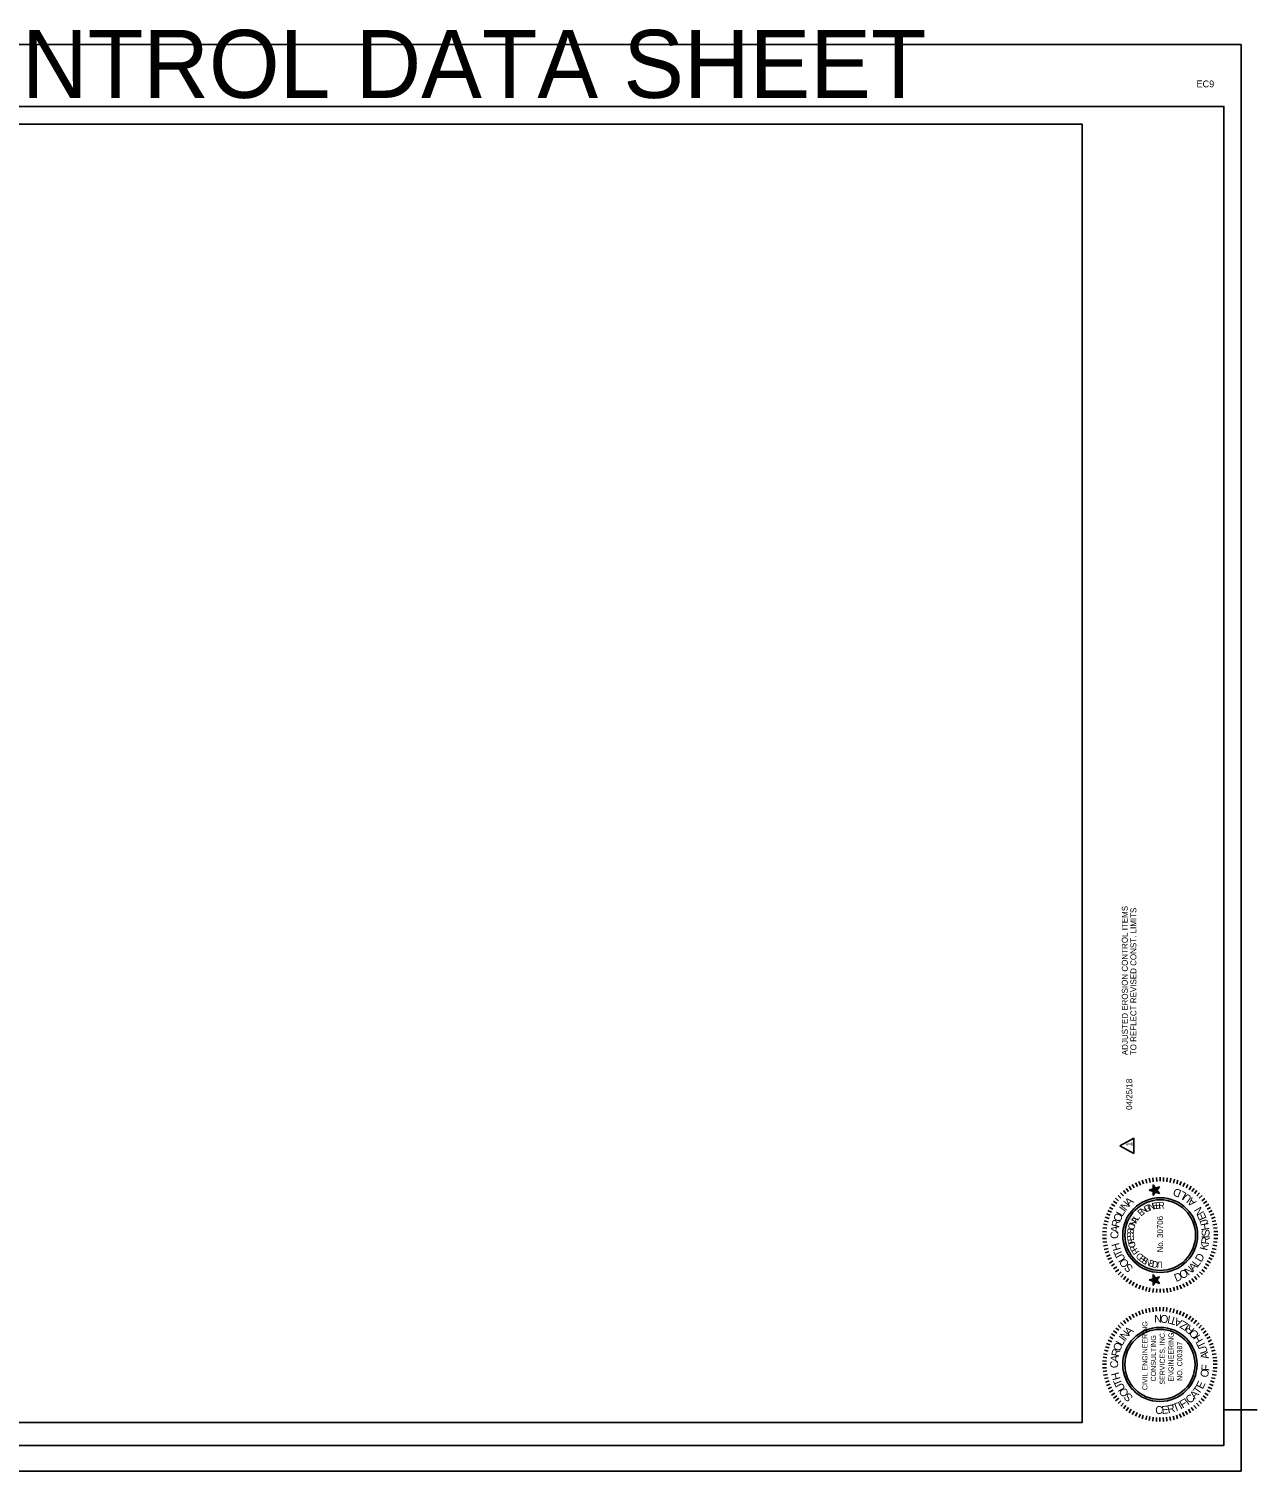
# Model space of a CAD drawing. Extents: x 260980 to 262786, y 322333 to 323393.
import ezdxf

# ---------------------------------------------------------------- set-up
doc = ezdxf.new("R2010")
doc.units = 0
for name, color, linetype in [('Level 1', 7, 'Continuous'), ('Level 2', 7, 'Continuous'), ('Level 23', 7, 'Continuous'), ('Level 3', 7, 'Continuous'), ('Level 4', 7, 'Continuous'), ('Level 8', 7, 'Continuous'), ('RD_SHT_SEAL_KA', 7, 'Continuous'), ('RD_SHT_TX', 7, 'Continuous')]:
    doc.layers.add(name, color=color, linetype=linetype)

msp = doc.modelspace()

# ---------------------------------------------------------------- linework, layer by layer
at = {"layer": 'Level 1'}
msp.add_lwpolyline([(261216, 323323.3), (262657.4, 323323.3), (262657.4, 322368.7), (261216, 322368.7)], close=True, dxfattribs=at)
at = {"layer": 'Level 2'}
msp.add_lwpolyline([(261216, 322368.7), (262657.4, 322368.7), (262657.4, 323323.3), (261216, 323323.3)], close=True, dxfattribs=at)
at = {"layer": 'Level 23'}
msp.add_lwpolyline([(261111.1, 323336.4), (262761.5, 323336.4), (262761.5, 322351.8), (261111.1, 322351.8)], close=True, dxfattribs=at)
msp.add_lwpolyline([(261111.1, 323336.4), (262761.5, 323336.4), (262761.5, 322351.8), (261111.1, 322351.8)], close=True, dxfattribs=at)
at = {"layer": 'Level 3'}
for p, q in [((261099.2, 323381.9), (262774.2, 323381.9)), ((262774.2, 322332.8), (262774.2, 323381.9)), ((261099.2, 322332.9), (262774.2, 322332.9))]:
    msp.add_line(p, q, dxfattribs=at)
at = {"layer": 'Level 4'}
msp.add_line((262762, 322377.8), (262786, 322377.8), dxfattribs=at)
at = {"layer": 'RD_SHT_SEAL_KA'}
for p, q in [((262694.2, 322543.6), (262695.6, 322541.1)), ((262696.6, 322544.8), (262697.9, 322542.2)), ((262699, 322545.9), (262700.1, 322543.2)), ((262701.5, 322546.8), (262702.5, 322544.1)), ((262704.1, 322547.6), (262704.8, 322544.7)), ((262706.7, 322548.2), (262707.3, 322545.2)), ((262709.4, 322548.6), (262709.6, 322545.7)), ((262712, 322548.7), (262712.2, 322545.9)), ((262714.7, 322548.9), (262714.6, 322546)), ((262717.2, 322548.7), (262717.1, 322545.9)), ((262719.9, 322548.5), (262719.7, 322545.6)), ((262722.6, 322548.2), (262722.1, 322545.2)), ((262725.2, 322547.6), (262724.4, 322544.7)), ((262727.7, 322546.8), (262726.9, 322544.1)), ((262730.2, 322545.9), (262729.2, 322543.1)), ((262732.7, 322544.8), (262731.4, 322542.2)), ((262735.1, 322543.6), (262733.7, 322541.1)), ((262681.9, 322533.5), (262684.1, 322531.6)), ((262683.7, 322535.5), (262685.8, 322533.6)), ((262685.6, 322537.4), (262687.6, 322535.2)), ((262687.6, 322539.1), (262689.4, 322536.9)), ((262689.7, 322540.7), (262691.4, 322538.4)), ((262691.9, 322542.3), (262693.4, 322539.8)), ((262737.4, 322542.3), (262735.9, 322539.8)), ((262739.6, 322540.8), (262737.9, 322538.4)), ((262741.7, 322539.2), (262739.8, 322536.9)), ((262743.7, 322537.4), (262741.7, 322535.3)), ((262745.6, 322535.5), (262743.4, 322533.5)), ((262747.4, 322533.4), (262745.2, 322531.6)), ((262675.2, 322522.1), (262677.9, 322521)), ((262676.3, 322524.4), (262678.9, 322523.2)), ((262677.4, 322526.8), (262679.9, 322525.5)), ((262678.9, 322529.2), (262681.3, 322527.6)), ((262680.3, 322531.4), (262682.7, 322529.7)), ((262748.9, 322531.4), (262746.6, 322529.7)), ((262750.5, 322529.1), (262748.1, 322527.6)), ((262751.8, 322526.8), (262749.3, 322525.5)), ((262753, 322524.6), (262750.4, 322523.3)), ((262754.1, 322522.1), (262751.4, 322521)), ((262672.5, 322511.8), (262675.5, 322511.4)), ((262673, 322514.4), (262675.8, 322513.9)), ((262673.6, 322517), (262676.4, 322516.2)), ((262674.3, 322519.5), (262677.1, 322518.7)), ((262755, 322519.5), (262752.3, 322518.7)), ((262755.7, 322517), (262752.9, 322516.3)), ((262756.3, 322514.4), (262753.5, 322513.9)), ((262756.7, 322511.7), (262753.9, 322511.4)), ((262672.3, 322509), (262675.3, 322508.8)), ((262672.3, 322506.5), (262675.1, 322506.4)), ((262672.3, 322503.8), (262675.2, 322503.9)), ((262672.6, 322501.2), (262675.4, 322501.5)), ((262756.7, 322501.1), (262753.9, 322501.5)), ((262757.1, 322509.1), (262754.1, 322509)), ((262757, 322503.8), (262754.1, 322504)), ((262757, 322506.5), (262754.2, 322506.5)), ((262673, 322498.5), (262675.9, 322499)), ((262673.6, 322495.8), (262676.4, 322496.6)), ((262674.3, 322493.3), (262677, 322494.3)), ((262675.2, 322490.8), (262677.9, 322491.9)), ((262754.1, 322490.8), (262751.4, 322491.9)), ((262755, 322493.3), (262752.2, 322494.2)), ((262755.8, 322495.9), (262752.9, 322496.5)), ((262756.3, 322498.5), (262753.4, 322499)), ((262676.3, 322488.4), (262678.9, 322489.6)), ((262677.4, 322485.9), (262680, 322487.4)), ((262678.9, 322483.7), (262681.2, 322485.2)), ((262680.4, 322481.5), (262682.7, 322483.2)), ((262681.9, 322479.4), (262684.2, 322481.2)), ((262683.7, 322477.3), (262685.9, 322479.4)), ((262745.7, 322477.5), (262743.5, 322479.4)), ((262747.3, 322479.4), (262745.2, 322481.2)), ((262748.9, 322481.5), (262746.7, 322483.2)), ((262750.5, 322483.7), (262748, 322485.2)), ((262751.8, 322486), (262749.3, 322487.4)), ((262753, 322488.4), (262750.4, 322489.6)), ((262685.7, 322475.5), (262687.6, 322477.6)), ((262687.6, 322473.7), (262689.4, 322476)), ((262689.7, 322472.1), (262691.4, 322474.5)), ((262691.9, 322470.6), (262693.5, 322473.1)), ((262694.2, 322469.3), (262695.6, 322471.8)), ((262696.6, 322468), (262697.8, 322470.6)), ((262699, 322467), (262700.1, 322469.7)), ((262701.6, 322466.1), (262702.5, 322468.8)), ((262727.7, 322466.1), (262726.9, 322468.8)), ((262730.3, 322466.9), (262729.2, 322469.7)), ((262732.7, 322468.1), (262731.4, 322470.7)), ((262735.1, 322469.2), (262733.7, 322471.8)), ((262737.4, 322470.7), (262735.9, 322473)), ((262739.6, 322472.1), (262737.9, 322474.4)), ((262741.7, 322473.7), (262739.9, 322476)), ((262743.7, 322475.5), (262741.7, 322477.6)), ((262704.1, 322465.3), (262704.8, 322468.2)), ((262706.7, 322464.8), (262707.2, 322467.6)), ((262709.4, 322464.3), (262709.7, 322467.2)), ((262712, 322464.1), (262712.2, 322467)), ((262714.7, 322464.1), (262714.7, 322466.9)), ((262717.3, 322464.1), (262717.1, 322466.9)), ((262720, 322464.3), (262719.6, 322467.3)), ((262722.6, 322464.7), (262722.1, 322467.5)), ((262725.2, 322465.4), (262724.5, 322468.1)), ((262694.1, 322448.3), (262695.6, 322445.7)), ((262696.5, 322449.3), (262697.7, 322446.9)), ((262698.9, 322450.4), (262700, 322447.8)), ((262701.4, 322451.4), (262702.3, 322448.6)), ((262704.1, 322452.1), (262704.6, 322449.3)), ((262706.6, 322452.6), (262707.2, 322449.8)), ((262709.2, 322453.2), (262709.6, 322450.1)), ((262711.8, 322453.3), (262712, 322450.4)), ((262714.4, 322453.3), (262714.5, 322450.6)), ((262717.1, 322453.3), (262716.9, 322450.4)), ((262719.7, 322453.1), (262719.4, 322450.2)), ((262722.4, 322452.6), (262721.9, 322449.8)), ((262724.9, 322452.1), (262724.2, 322449.3)), ((262727.4, 322451.3), (262726.6, 322448.6)), ((262729.9, 322450.4), (262728.9, 322447.8)), ((262732.3, 322449.4), (262731.2, 322446.9)), ((262734.8, 322448.2), (262733.4, 322445.6)), ((262682, 322438.1), (262684.3, 322436.4)), ((262683.8, 322440.1), (262685.8, 322438.1)), ((262685.6, 322442.1), (262687.6, 322439.9)), ((262687.6, 322443.7), (262689.5, 322441.5)), ((262689.7, 322445.4), (262691.4, 322443)), ((262691.9, 322446.9), (262693.4, 322444.4)), ((262737.2, 322446.9), (262735.5, 322444.4)), ((262739.3, 322445.3), (262737.5, 322443)), ((262741.3, 322443.8), (262739.5, 322441.5)), ((262743.3, 322442), (262741.3, 322439.9)), ((262745.1, 322440.1), (262743, 322438.1)), ((262747, 322438.1), (262744.7, 322436.4)), ((262675.3, 322426.8), (262678, 322425.8)), ((262676.4, 322429.2), (262679.1, 322428)), ((262677.6, 322431.6), (262680, 322430.1)), ((262679, 322433.9), (262681.4, 322432.3)), ((262680.3, 322436), (262682.7, 322434.3)), ((262748.5, 322436), (262746.3, 322434.4)), ((262750, 322433.8), (262747.6, 322432.3)), ((262751.4, 322431.6), (262748.9, 322430.3)), ((262752.5, 322429.3), (262749.9, 322428)), ((262753.6, 322426.8), (262750.9, 322425.7)), ((262672.7, 322416.6), (262675.5, 322416.2)), ((262673.1, 322419.2), (262675.8, 322418.7)), ((262673.7, 322421.8), (262676.5, 322421.1)), ((262674.4, 322424.3), (262677.2, 322423.5)), ((262754.5, 322424.3), (262751.8, 322423.4)), ((262755.2, 322421.8), (262752.4, 322421.1)), ((262755.8, 322419.1), (262753, 322418.7)), ((262756.3, 322416.5), (262753.4, 322416.2)), ((262672.3, 322411.4), (262675.2, 322411.4)), ((262672.4, 322414), (262675.3, 322413.8)), ((262672.4, 322408.7), (262675.3, 322408.9)), ((262672.8, 322406.1), (262675.5, 322406.5)), ((262756.3, 322406), (262753.4, 322406.5)), ((262756.5, 322414), (262753.6, 322413.9)), ((262756.5, 322408.8), (262753.6, 322408.9)), ((262756.5, 322411.4), (262753.7, 322411.4)), ((262673.1, 322403.5), (262676, 322404)), ((262673.7, 322400.9), (262676.5, 322401.5)), ((262674.5, 322398.3), (262677.2, 322399.2)), ((262675.3, 322395.9), (262678, 322396.9)), ((262676.4, 322393.4), (262679, 322394.7)), ((262752.6, 322393.4), (262749.9, 322394.6)), ((262753.6, 322395.8), (262751, 322396.9)), ((262754.5, 322398.3), (262751.8, 322399.2)), ((262755.2, 322400.9), (262752.4, 322401.5)), ((262755.8, 322403.5), (262753, 322404)), ((262677.5, 322391), (262680.1, 322392.4)), ((262679, 322388.8), (262681.3, 322390.3)), ((262680.4, 322386.6), (262682.7, 322388.2)), ((262681.9, 322384.6), (262684.3, 322386.4)), ((262683.8, 322382.5), (262685.8, 322384.6)), ((262745.1, 322382.6), (262743, 322384.6)), ((262747, 322384.6), (262744.7, 322386.3)), ((262748.5, 322386.6), (262746.2, 322388.3)), ((262750, 322388.8), (262747.6, 322390.3)), ((262751.4, 322391.1), (262748.9, 322392.5)), ((262685.7, 322380.7), (262687.6, 322382.9)), ((262687.6, 322378.8), (262689.5, 322381.1)), ((262689.7, 322377.3), (262691.4, 322379.6)), ((262691.9, 322375.8), (262693.4, 322378.3)), ((262694.2, 322374.5), (262695.6, 322376.9)), ((262696.5, 322373.3), (262697.7, 322375.9)), ((262699, 322372.2), (262700.1, 322374.8)), ((262701.5, 322371.3), (262702.3, 322374.1)), ((262704.1, 322370.6), (262704.8, 322373.4)), ((262725, 322370.6), (262724.2, 322373.3)), ((262727.4, 322371.4), (262726.6, 322374.1)), ((262730, 322372.2), (262728.9, 322374.9)), ((262732.5, 322373.3), (262731.1, 322376)), ((262734.8, 322374.5), (262733.3, 322376.9)), ((262737, 322375.8), (262735.5, 322378.3)), ((262739.3, 322377.4), (262737.5, 322379.6)), ((262741.3, 322378.9), (262739.5, 322381.1)), ((262743.3, 322380.7), (262741.3, 322382.9)), ((262706.6, 322370), (262707.1, 322372.9)), ((262709.2, 322369.6), (262709.6, 322372.5)), ((262711.9, 322369.4), (262712.1, 322372.2)), ((262714.4, 322369.4), (262714.5, 322372.2)), ((262717.1, 322369.4), (262716.9, 322372.3)), ((262719.7, 322369.6), (262719.4, 322372.5)), ((262722.3, 322370), (262721.8, 322372.8))]:
    msp.add_line(p, q, dxfattribs=at)
for points in [[(262706.7, 322539.5), (262709.5, 322538.5), (262709.6, 322535.7), (262711.3, 322538.1), (262714.1, 322537.1), (262712.3, 322539.5), (262714.1, 322541.9), (262711.3, 322540.9), (262709.5, 322543.3), (262709.5, 322540.4)], [(262707.1, 322539.5), (262709.6, 322538.7), (262709.7, 322536), (262711.3, 322538.2), (262713.8, 322537.4), (262712.3, 322539.5), (262713.8, 322541.7), (262711.3, 322540.9), (262709.6, 322543), (262709.7, 322540.3)], [(262707.5, 322539.5), (262709.8, 322538.8), (262709.8, 322536.4), (262711.2, 322538.3), (262713.5, 322537.6), (262712.1, 322539.5), (262713.5, 322541.5), (262711.3, 322540.7), (262709.7, 322542.6), (262709.8, 322540.3)], [(262707.9, 322539.5), (262710, 322538.9), (262710, 322536.8), (262711.1, 322538.5), (262713.1, 322537.7), (262711.9, 322539.5), (262713.1, 322541.2), (262711.1, 322540.5), (262709.9, 322542.3), (262709.9, 322540.2)], [(262708.3, 322539.5), (262710.1, 322538.9), (262710, 322537.1), (262711, 322538.5), (262712.9, 322538.1), (262711.8, 322539.5), (262712.8, 322540.9), (262711.1, 322540.4), (262710.1, 322541.9), (262710, 322540.1)], [(262708.7, 322539.6), (262710.1, 322539), (262710.1, 322537.5), (262711, 322538.8), (262712.5, 322538.2), (262711.6, 322539.5), (262712.5, 322540.7), (262711.1, 322540.3), (262710.2, 322541.5), (262710.1, 322540)], [(262709.1, 322539.5), (262710.2, 322539.1), (262710.3, 322537.8), (262711, 322538.9), (262712.2, 322538.5), (262711.4, 322539.5), (262712.2, 322540.5), (262711, 322540.1), (262710.3, 322541.2), (262710.2, 322539.9)], [(262709.5, 322539.5), (262710.4, 322539.2), (262710.4, 322538.2), (262711, 322539), (262711.8, 322538.7), (262711.4, 322539.5), (262711.9, 322540.3), (262711, 322540), (262710.4, 322540.7), (262710.4, 322539.8)], [(262709.8, 322539.5), (262710.5, 322539.2), (262710.6, 322538.7), (262710.9, 322539.1), (262711.5, 322538.9), (262711.2, 322539.5), (262711.6, 322540.1), (262711, 322539.8), (262710.6, 322540.4), (262710.5, 322539.8)], [(262710.2, 322539.5), (262710.6, 322539.4), (262710.6, 322539), (262710.9, 322539.4), (262711.3, 322539.1), (262711, 322539.6), (262711.3, 322539.8), (262710.9, 322539.7), (262710.6, 322540.1), (262710.7, 322539.7)], [(262710.7, 322539.6), (262710.8, 322539.5), (262710.8, 322539.4), (262710.8, 322539.4), (262711, 322539.4), (262710.9, 322539.5), (262710.9, 322539.6), (262710.8, 322539.6), (262710.8, 322539.6), (262710.8, 322539.5)], [(262706.7, 322473.4), (262709.6, 322472.4), (262709.6, 322469.5), (262711.4, 322471.9), (262714.1, 322470.9), (262712.3, 322473.4), (262714.1, 322475.7), (262711.3, 322474.8), (262709.5, 322477.2), (262709.5, 322474.3)], [(262707.1, 322473.3), (262709.6, 322472.6), (262709.6, 322469.9), (262711.3, 322472), (262713.8, 322471.2), (262712.2, 322473.3), (262713.8, 322475.5), (262711.2, 322474.7), (262709.7, 322476.9), (262709.6, 322474.2)], [(262707.5, 322473.4), (262709.8, 322472.6), (262709.8, 322470.2), (262711.2, 322472.2), (262713.5, 322471.5), (262712.1, 322473.4), (262713.5, 322475.3), (262711.1, 322474.5), (262709.8, 322476.5), (262709.8, 322474.1)], [(262707.9, 322473.4), (262709.9, 322472.7), (262710, 322470.6), (262711.1, 322472.3), (262713.1, 322471.7), (262711.9, 322473.3), (262713.1, 322475.1), (262711.1, 322474.5), (262709.8, 322476.1), (262710, 322474)], [(262708.3, 322473.4), (262710, 322472.8), (262710.1, 322471), (262711.1, 322472.4), (262712.9, 322471.9), (262711.7, 322473.4), (262712.9, 322474.9), (262711.1, 322474.3), (262710, 322475.7), (262710, 322474)], [(262708.7, 322473.4), (262710.2, 322472.9), (262710.1, 322471.4), (262711, 322472.6), (262712.5, 322472.1), (262711.6, 322473.4), (262712.5, 322474.7), (262711, 322474.1), (262710.2, 322475.4), (262710.2, 322473.9)], [(262709.1, 322473.4), (262710.2, 322473), (262710.4, 322471.7), (262711, 322472.8), (262712.2, 322472.4), (262711.5, 322473.3), (262712.2, 322474.4), (262711, 322474.1), (262710.3, 322475), (262710.3, 322473.7)], [(262709.5, 322473.4), (262710.4, 322473.1), (262710.4, 322472.1), (262710.9, 322472.9), (262711.8, 322472.6), (262711.4, 322473.4), (262711.9, 322474.2), (262711, 322473.9), (262710.4, 322474.7), (262710.3, 322473.6)], [(262709.9, 322473.4), (262710.5, 322473.1), (262710.5, 322472.4), (262710.9, 322473), (262711.5, 322472.9), (262711.1, 322473.4), (262711.6, 322473.9), (262710.9, 322473.7), (262710.6, 322474.3), (262710.5, 322473.6)], [(262710.2, 322473.4), (262710.6, 322473.2), (262710.6, 322472.9), (262710.9, 322473.2), (262711.3, 322473), (262711, 322473.4), (262711.3, 322473.6), (262710.8, 322473.5), (262710.7, 322473.9), (262710.7, 322473.5)], [(262710.7, 322473.4), (262710.8, 322473.4), (262710.8, 322473.1), (262710.8, 322473.3), (262710.9, 322473.3), (262710.9, 322473.4), (262710.9, 322473.4), (262710.8, 322473.4), (262710.7, 322473.6), (262710.7, 322473.4)]]:
    msp.add_lwpolyline(points, close=True, dxfattribs=at)
for radius in [27.5, 26]:
    msp.add_circle((262714.7, 322506.4), radius, dxfattribs=at)
for major_axis in [(-27.3, 0), (-25.8, 0)]:
    msp.add_ellipse((262714.5, 322411.3), major_axis=major_axis, ratio=0.998589, dxfattribs=at)
at = {"layer": 'RD_SHT_TX'}
for p, q in [((262695.3, 322577.8), (262685.1, 322572.1)), ((262695.3, 322566.4), (262695.3, 322577.8)), ((262685.1, 322572.1), (262695.3, 322566.4))]:
    msp.add_line(p, q, dxfattribs=at)

# ---------------------------------------------------------------- texts
at = {"layer": 'Level 3'}
msp.add_text('EC9', height=5, dxfattribs=at).set_placement((262741.4, 323350.5))
at = {"layer": 'Level 8'}
msp.add_text('EROSION CONTROL DATA SHEET', height=50, dxfattribs=at).set_placement((261450.7, 323342.7))
at = {"layer": 'RD_SHT_SEAL_KA'}
for s, height, rotation, p in [('A', 5.79, 43.0946, (262691.9, 322527.2)), ('D', 5.78, 157.437, (262730.8, 322539.1)), ('L', 5.78, 150.6276, (262734.6, 322537)), ('U', 5.78, 143.1014, (262738.4, 322534.1)), ('A', 5.78, 135.9336, (262741.7, 322530.9)), ('O', 5.79, 68.1426, (262685.3, 322515.6)), ('L', 5.79, 59.9125, (262686.9, 322519.7)), ('I', 5.79, 53.1138, (262688.7, 322522.9)), ('N', 5.79, 50.609, (262689.4, 322524.1)), ('E', 4.82, 42.0319, (262700.7, 322520)), ('N', 4.82, 35.5788, (262702.3, 322521.4)), ('G', 4.82, 28.803, (262704.2, 322522.8)), ('I', 4.82, 21.7046, (262706.3, 322524)), ('N', 4.82, 19.446, (262707, 322524.3)), ('E', 4.82, 12.6702, (262709.1, 322525.1)), ('E', 4.82, 6.2171, (262711.3, 322525.6)), ('R', 4.82, 359.764, (262713.4, 322525.8)), ('N', 5.78, 120.8215, (262747.1, 322523)), ('E', 5.78, 113.6537, (262748.9, 322518.8)), ('A', 5.79, 82.8136, (262683.9, 322507.9)), ('R', 5.79, 75.657, (262684.3, 322511.7)), ('I', 4.82, 77.9004, (262695.4, 322509.2)), ('O', 4.82, 75.6418, (262695.5, 322510)), ('N', 4.82, 68.2207, (262696.1, 322512.4)), ('A', 4.82, 61.445, (262697, 322514.5)), ('L', 4.82, 54.9919, (262698, 322516.5)), ('No. 30706', 4.34, 90, (262716.8, 322493.7)), ('J', 5.78, 107.5611, (262750.1, 322515.1)), ('H', 5.78, 100.0349, (262750.9, 322510.4)), ('C', 5.79, 90.6858, (262684, 322503.7)), ('S', 4.82, 91.452, (262695.3, 322504.6)), ('E', 4.82, 97.9051, (262695.6, 322502.4)), ('S', 4.82, 84.6762, (262695.2, 322506.9)), ('F', 4.82, 104.3582, (262696.2, 322500.3)), ('O', 4.82, 111.7793, (262697.1, 322498)), ('K', 5.78, 74.9476, (262749.2, 322494.7)), ('R', 5.78, 82.4738, (262750.4, 322499.3)), ('S', 5.78, 92.5087, (262751.1, 322505.6)), ('I', 5.78, 90, (262751, 322504)), ('H', 5.79, 105.7743, (262685.8, 322495.8)), ('T', 5.79, 113.2887, (262687.4, 322492.1)), ('U', 5.79, 120.8031, (262689.5, 322488.7)), ('R', 4.82, 118.555, (262698.2, 322496)), ('P', 4.82, 125.3308, (262699.6, 322494.1)), ('D', 4.82, 138.9361, (262702.9, 322490.9)), ('E', 4.82, 145.3892, (262704.7, 322489.7)), ('S', 4.82, 152.165, (262706.7, 322488.6)), ('D', 5.78, 59.8355, (262744.9, 322486.1)), ('O', 5.79, 129.0332, (262692.3, 322485.3)), ('S', 5.79, 136.5476, (262695.3, 322482.5)), ('N', 4.82, 158.9407, (262708.9, 322487.8)), ('E', 4.82, 165.3939, (262711, 322487.3)), ('C', 4.82, 172.4923, (262713.4, 322487)), ('I', 4.82, 174.7509, (262714.2, 322486.9)), ('L', 4.82, 180.8813, (262716.3, 322487)), ('O', 5.78, 30.0892, (262730.8, 322473.8)), ('N', 5.78, 38.3321, (262735.3, 322476.4)), ('A', 5.78, 45.8583, (262739.1, 322479.4)), ('L', 5.78, 53.0261, (262742.3, 322482.6)), ('D', 5.78, 22.563, (262726.4, 322471.9)), ('N', 5.79, 181.8428, (262715.8, 322447.9)), ('O', 5.79, 173.6128, (262721, 322447.3)), ('A', 5.79, 43.0946, (262691.8, 322432.1)), ('CIVIL ENGINEERING', 3.751, 89.9897, (262705.3, 322392.4)), ('I', 5.79, 171.108, (262722.6, 322447)), ('T', 5.79, 163.5935, (262727.2, 322445.6)), ('A', 5.79, 156.437, (262731.3, 322443.8)), ('Z', 5.79, 148.9225, (262735.4, 322441.3)), ('I', 5.79, 146.4177, (262736.7, 322440.3)), ('R', 5.79, 138.9033, (262740.3, 322437.2)), ('O', 5.79, 68.1426, (262685.1, 322420.5)), ('L', 5.79, 59.9125, (262686.7, 322424.6)), ('I', 5.79, 53.1138, (262688.5, 322427.8)), ('N', 5.79, 50.609, (262689.2, 322429)), ('CONSULTING', 3.75, 89.9897, (262711.6, 322398.8)), ('SERVICES, INC.', 3.751, 89.9897, (262718.1, 322396.4)), ('ENGINEERING', 3.751, 89.9897, (262724.5, 322398.6)), ('NO. C00387', 3.75, 89.9897, (262730.9, 322399.2)), ('O', 5.79, 130.6733, (262743.7, 322433.2)), ('H', 5.79, 123.1588, (262746.4, 322429.2)), ('T', 5.79, 115.6444, (262748.4, 322424.9)), ('A', 5.79, 82.8136, (262683.7, 322412.8)), ('R', 5.79, 75.657, (262684.2, 322416.6)), ('U', 5.79, 108.13, (262749.9, 322420.3)), ('A', 5.79, 100.9734, (262750.7, 322415.8)), ('C', 5.79, 90.6858, (262683.8, 322408.6)), ('H', 5.79, 105.7743, (262685.6, 322400.7)), ('O', 5.79, 78.0127, (262749.6, 322401.3)), ('F', 5.79, 86.2428, (262750.7, 322406.4)), ('T', 5.79, 113.2887, (262687.2, 322397)), ('U', 5.79, 120.8031, (262689.3, 322393.6)), ('T', 5.79, 55.7677, (262743.2, 322388.8)), ('E', 5.79, 63.2821, (262745.9, 322392.7)), ('O', 5.79, 129.0332, (262692.1, 322390.2)), ('S', 5.79, 136.5476, (262695.1, 322387.4)), ('F', 5.79, 31.0775, (262731.1, 322378.8)), ('I', 5.79, 38.234, (262735.1, 322381.1)), ('C', 5.79, 40.7388, (262736.4, 322382.1)), ('A', 5.79, 48.6111, (262740.2, 322385.4)), ('C', 5.79, 358.515, (262711, 322375)), ('E', 5.79, 6.3872, (262716, 322374.8)), ('R', 5.79, 13.5438, (262720.6, 322375.3)), ('T', 5.79, 21.0582, (262725.2, 322376.4)), ('I', 5.79, 28.5727, (262729.7, 322378.1))]:
    msp.add_text(s, height=height, rotation=rotation, dxfattribs=at).set_placement(p)
at = {"layer": 'RD_SHT_TX'}
for s, p in [('ADJUSTED EROSION CONTROL ITEMS ', (262690.9, 322638.7)), ('TO REFLECT REVISED CONST. LIMITS', (262697.2, 322638.7)), ('04/25/18', (262694.1, 322598.5)), ('1', (262694.1, 322571.6))]:
    msp.add_text(s, height=4.4, rotation=90.0016, dxfattribs=at).set_placement(p)

doc.saveas('drawing.dxf')
